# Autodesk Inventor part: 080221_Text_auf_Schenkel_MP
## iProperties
Created: 2008-02
Part Number: 080221_Text_auf_Schenkel_MP
Material: S355NC
Document SubType Name: Blech
Designer: knowhow1984
Mass: 10134.5 g
Surface Area: 4609.21 cm^2
Volume: 1289.37 cm^3
Density: 7.86 g/cm^3
SaveDate: 2007-04-09
SaveTime: 09:40
FileName: Kantblech_2_Winkel
TotalMass: 8,5 kg
TotalVolume: 1081647,3 mm^3
SM_Thickness: 6 mm
SM_Style: Norm
SM_Extents: N/A
SM_Extents_Width: 0,000 mm
SM_Extents_Length: 0,000 mm
Author: knowhow1984
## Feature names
1. Extrusion1
2. Biegung1
3. Biegung2
4. Ausklinkung1
